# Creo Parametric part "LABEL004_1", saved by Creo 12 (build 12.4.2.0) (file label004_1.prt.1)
Units: Custom; MM, KILOGRAM, SECS

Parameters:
  PTC_WM_ITERATION = "0"
  PTC_WM_VERSION = "-.0"
  PTC_WM_LIFECYCLE_STATE = "In Work"
  PTC_WM_LIFECYCLE = "MO_CADDocument"
  PTC_WM_CREATED_BY = "Maximilian Roepper (Z0017RMS: MO)"
  PTC_WM_CREATED_ON = "18-Sep-26 11:36:42 AM"
  PTC_WM_MODIFIED_BY = "Maximilian Roepper (Z0017RMS: MO)"
  PTC_WM_MODIFIED_ON = "18-Sep-26 11:36:46 AM"
  PDMLINKNUMBER = "PDM000071455229"
  PTC_WM_NAME = "label004_1.prt"
  PTC_WM_NUMBER = "PDM000071455229"

Other parameters: WEIGHT, WEIGHT_FACTOR, WEIGHT_ADD, _MASS_TEMP, _DIFF_TEMP, MC_ERRORS, SUPPLIER

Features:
  1. coordinate system
  2. datum plane "PRT_YZ"
  3. datum plane "PRT_XY"
  4. datum plane "PRT_XZ"
  5. coordinate system
  6. datum axis
  7. datum axis
  8. datum axis
  9. coordinate system
  10. imported feature

Other named items: PRT, SIEMENS_MO, DRW_VIEW_ORG, PRT_X, PRT_Y, PRT_Z, CS0, ROUGH_GROB

Layers: 00_STD_CSYS-KSYS, 01_STD_PLANES-EBENEN, 02_STD_AXES-ACHSEN, 03_STD_CSYS-KSYS, 24_IMPORT_FEAT-IMPORT_KE

Surfaces: 6 plane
